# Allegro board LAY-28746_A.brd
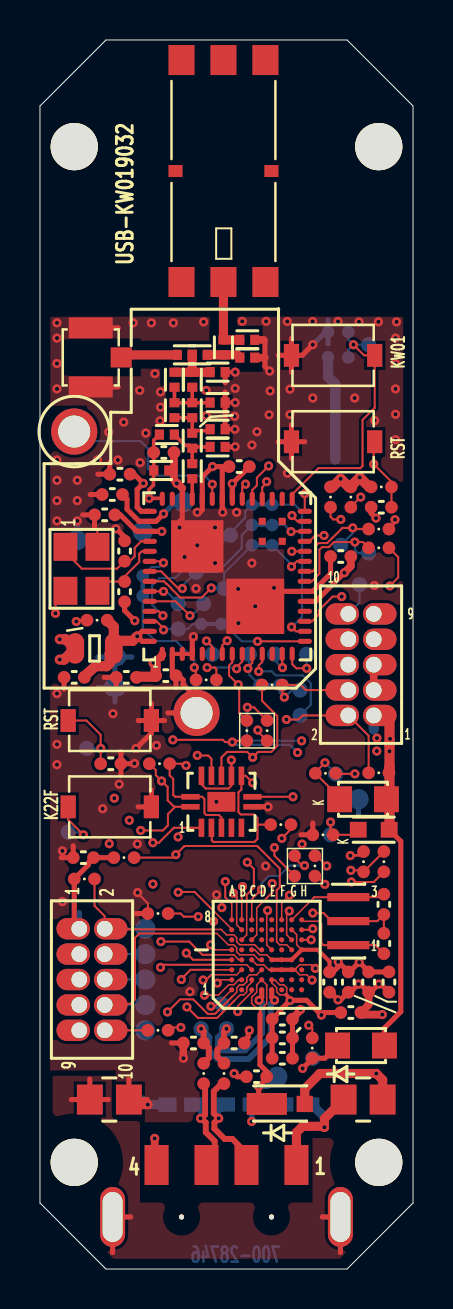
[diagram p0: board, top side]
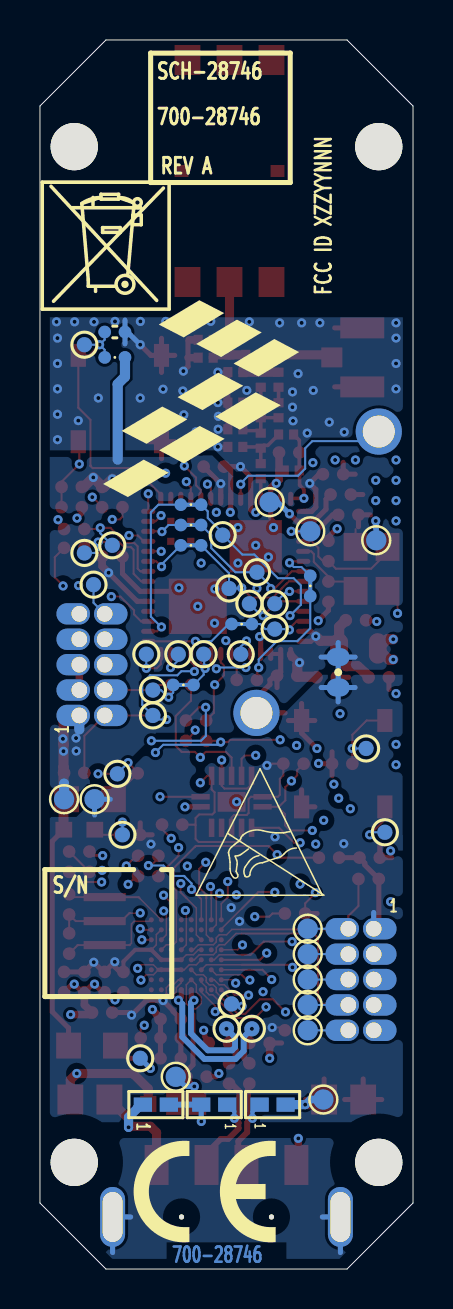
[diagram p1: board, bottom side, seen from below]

Outline 18.67 x 61.47 mm; copper layers: TOP, GND, SIGNAL, BOTTOM. Coordinates in mm from the lower left corner of the outline.
Outline path: 0,58.17 0,3.3 3.3,0 15.37,0 18.67,3.3 18.67,58.17 15.37,61.47 3.3,61.47 0,58.17

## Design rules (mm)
net group GA[0:7]: nets SWD_CLK_TGTMCU
net group GC[0:15]: nets RESET_TGTMCU_B
net group RF_7CLR: nets N23870337 N23870339 N23870349 RFIO
net group RF_18CLR: nets N23948926 N24026304 N24026588 RFIO_EXT
nets with their own width: min track width 0.254; nets VCC

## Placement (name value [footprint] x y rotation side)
ANT1  7488910092  [ANT_7488910092]  9.18 54.91 270 top
C4  5.6PF  [0402_CC]  8.89 44.86 0 top
C7  10PF  [0402_CC]  6.73 44.48 270 top
C9  7.5PF  [0402_CC]  8.89 43.33 0 top
C11  10PF  [0402_CC]  6.73 42.95 270 top
C13  6.8PF  [0402_CC]  7.62 41.43 90 top
C14  0.1UF  [CC0402_25]  6.2 40.84 0 top
C15  2.0PF  [0402_CC]  8.89 41.12 0 top
C16  220PF  [0402_CC]  6.07 39.94 0 top
C17  3.3PF  [0402_CC]  10.38 45.58 0 top
C19  0.1UF  [CC0402_25]  9.97 40.13 180 top
C20  3.3PF  [0402_CC]  10.38 46.47 0 top
C21  11PF  [CC0402_25]  4.23 35.91 90 top
C22  11PF  [CC0402_25]  4.23 33.88 270 top
C23  18PF  [CC0402_25]  17.21 16.28 270 top
C24  18PF  [CC0402_25]  17.21 18.24 90 top
C25  0.1UF  [CC0402_25]  4 39.75 180 top
C26  0.1UF  [CC0402_25]  4.32 29.59 180 top
C27  10UF  [CC0805_OV]  2.73 31.04 180 top
C28  0.1UF  [CC0402_25]  3.24 37.72 180 top
C31  0.1UF  [CC0402_25]  16.45 14.35 270 top
C32  2.2UF  [CC0402_25]  15.56 12.83 0 top
C33  0.1UF  [CC0402_25]  15.43 14.35 270 top
C34  0.1UF  [CC0402_25]  17.46 14.35 270 top
C36  0.1UF  [CC0402_25]  6.3 29.68 0 top
C37  47PF  [CC0402_25]  7.68 11.3 180 top
C38  47PF  [CC0402_25]  9.72 11.3 0 top
C39  0.1UF  [CC0402_25]  12.13 10.54 0 top
C42  0.1UF  [CC0402_25]  15.05 35.64 180 top
C43  0.01UF  [CC0402_25]  1.71 29.59 180 top
C44  0.1UF  [CC0402_25]  3.62 38.74 180 top
C46  10PF  [0402_CC]  8.89 42 0 top
C49  1.0UF  [CC0402_25]  10.84 9.62 180 top
C50  100PF  [0402_CC]  8 45.72 0 top
C51  1000PF  [CC0402_25]  14.92 46.86 180 bottom
C58  100PF  [0402_CC]  7.25 45.72 180 top
C60  1000PF  [CC0402_25]  17.08 38.1 180 top
C62  1000PF  [CC0402_25]  3.54 25.27 0 top
C66  0.1UF  [CC0402_25]  12.13 11.56 0 top
C67  0.1UF  [CC0402_25]  12.13 12.5 0 top
C68  0.1UF  [CC0402_25]  2.17 20.57 180 top
C69  0.01UF  [CC0402_25]  14.49 14.35 270 top
D4  GREEN  [LED_0603]  16.7 21.97 180 top
D8  BLUE  [LED2_2P34_2P1X1P25]  16.07 11.18 0 top
D12  BLUE  [LED2_2P34_2P1X1P25]  16.17 23.5 0 top
D18  MSS1P3L  [SMB_2P7X1P4]  12 8.26 0 top
J5  USB_TYPE_A  [MOLEX_480371000_USB_AM_SM]  9.33 2.6 0 top
J13  HDR 2X5  [CON_2RH_10_50]  1.97 17.02 270 top
J14  HDR 2X5  [CON_2RH_10_50]  16.7 27.69 90 top
J49  U.FL  [UFL_CONN3]  2.54 45.59 90 top
L2  0.0068UH  [0402_CC]  7.62 44.48 90 top
L3  10NH  [0402_CC]  9.18 46.09 90 top
L5  0.0068UH  [0402_CC]  7.62 42.95 90 top
L6  330 OHM  [IND_0805]  16.17 8.48 0 top
L7  330 OHM  [IND_0805]  3.47 8.48 0 top
L9  0.0047UH  [0402_CC]  7.62 39.9 90 top
L11  33nH  [0402_CC]  6.35 41.73 0 top
NOREF  -  []  -110.1 -101.68 0 top
NOREF#2  -  []  213.05 -126.24 0 top
NOREF#3  -  []  213 -99.57 0 top
NOREF#4  -  []  -105.39 -102.81 0 top
NOREF#5  -  []  0 56.24 0 top
NOREF#6  -  [unnamed#2]  16.95 5.33 0 top
NOREF#7  -  [unnamed#2]  1.71 56.13 0 top
NOREF#8  -  []  0 3.3 90 top
NOREF#9  -  []  -420.12 -277.37 0 top
NOREF#10  -  [unnamed#2]  1.71 5.33 0 top
NOREF#11  -  []  0 58.17 0 top
NOREF#12  -  []  3.3 61.47 0 top
NOREF#13  -  []  -208.12 -201.47 0 top
NOREF#14  -  []  -206.92 -205.2 0 top
NOREF#15  -  []  -39.12 -66.55 0 top
NOREF#16  -  []  167.39 109.22 0 top
NOREF#17  -  [unnamed#2]  16.95 56.13 0 top
NOREF#18  -  []  -207.76 -196.98 0 top
NOREF#19  -  []  3.3 0 90 top
NOREF#20  -  []  6.92 0 90 top
NOREF#21  -  []  -102.26 -96.66 0 top
NOREF#22  -  []  3.89 20.18 0 top
NOREF#23  -  []  -103.09 -101.68 0 top
NOREF#24  -  []  1.68 5.18 0 top
NOREF#25  -  []  -103.81 -197.14 0 top
NOREF#26  -  []  15.51 38.61 180 bottom
NOREF#27  -  []  12.97 1.02 180 bottom
NOREF#28  -  []  18.55 48.01 180 bottom
NOREF#29  -  []  10.83 18.69 180 bottom
R5  4.7K  [RC0402_25]  2.86 32.45 0 top
R10  220  [RC0402_25]  14.16 21.72 180 top
R11  0  [RC0402_25]  11.37 26.92 90 top
R14  0  [RC0402_25]  16.19 20.37 90 top
R15  0  [RC0402_25]  10.35 26.92 90 top
R17  0  [RC0402_25]  17.21 20.37 90 top
R25  10.0K  [RC0402_25]  16.95 24.82 0 top
R26  10.0K  [RC0402_25]  2.22 19.51 0 top
R30  220  [RC0402_25]  13.63 11.05 90 top
R31  220  [RC0402_25]  14.29 24.79 0 top
R50  33  [RC0402_25]  9.21 9.78 90 top
R51  33  [RC0402_25]  8.19 9.78 90 top
R53  4.7K  [RC0402_25]  15.56 38.61 270 top
R54  4.7K  [RC0402_25]  14.54 38.61 270 top
R85  100  [RC0402_25]  8.32 29.46 180 top
R88  1.0K  [RC0402_25]  12.74 20.16 90 top
R89  1.0K  [RC0402_25]  13.76 20.16 90 top
R90  1.0K  [RC0402_25]  16.95 37.01 180 top
R91  1.0K  [RC0402_25]  16.95 36.07 180 top
R92  1.0K  [RC0402_25]  12.05 22.23 0 top
R93  1.0K  [RC0402_25]  11.62 29.21 0 top
R105  10.0K  [RC0402_25]  5.98 25.27 0 top
R106  27K  [RC0402_25]  4.2 20.57 0 top
R112  27K  [RC0402_25]  5.91 17.78 180 top
R113  15K  [RC0402_25]  17.08 39.12 0 top
R114  15K  [RC0402_25]  5.91 11.94 180 top
R556  10.0K  [RC0402_25]  14.92 45.59 0 bottom
SH19  0  [RC0603_OV_CT]  3.75 29.85 90 bottom
SH40  0  [RC0402_25_CT]  11.11 37.21 0 bottom
SH41  0  [RC0402_25_CT]  11.11 36.2 0 bottom
SH44  0  [RC0402_25_CT]  5.14 34.16 90 bottom
SH45  0  [RC0402_25_CT]  8.57 32.26 0 bottom
SH46  0  [RC0402_25_CT]  11.11 38.23 0 bottom
SH47  0  [RC0402_25_CT]  11.49 29.21 180 bottom
SW1  TL1015AF160QG  [TL1015AF160QG_2P]  14.67 45.69 180 top
SW2  TL1015AF160QG  [TL1015AF160QG_2P]  3.49 23.11 0 top
SW5  TL1015AF160QG  [TL1015AF160QG_2P]  14.67 41.38 0 top
SW6  TL1015AF160QG  [TL1015AF160QG_2P]  3.49 27.43 180 top
TP2  -  [TPAD_040]  15.94 23.5 180 bottom
TP4  -  [TPAD_040]  17.46 23.5 180 bottom
TP8  -  [TPAD_030]  14.54 21.72 180 bottom
TP9  -  [TPAD_040]  1.84 36.45 180 bottom
TP10  -  [TPAD_040]  4.49 8.48 180 bottom
TP17  -  [TPAD_030]  13.65 10.54 180 bottom
TP21  -  [TPAD_030]  14.8 24.77 180 bottom
TP22  -  [TPAD_030]  9.33 12.01 180 bottom
TP23  -  [TPAD_030]  16.45 46.23 180 bottom
TP24  -  [TPAD_030]  8.62 30.75 180 bottom
TP25  -  [TPAD_030]  8.06 12.01 180 bottom
TP30  -  [TPAD_030]  1.41 21.84 180 bottom
TP32  -  [TPAD_030]  13.02 27.69 180 bottom
TP35  -  [TPAD_030]  15.99 34.23 180 bottom
TP36  -  [TPAD_030]  10.48 30.75 180 bottom
TP37  TESTLOOP_BLACK  [TP_TH_063]  1.71 41.88 0 top
TP42  -  [TPAD_030]  6.92 32 90 bottom
TP43  -  [TPAD_030]  9.53 36.7 180 bottom
TP44  -  [TPAD_030]  6.92 33.27 180 bottom
TP45  -  [TPAD_030]  8.19 33.27 180 bottom
TP46  -  [TPAD_040]  7.18 38.35 90 bottom
TP47  -  [TPAD_030]  9.21 34.04 90 bottom
TP48  -  [TPAD_040]  5.14 36.89 90 bottom
TP49  -  [TPAD_030]  7.81 34.85 180 bottom
TP51  -  [TPAD_030]  13.02 28.96 180 bottom
TP102  -  [TPAD_030]  9.08 13.26 0 bottom
TP104  -  [TPAD_040]  11.87 9.61 180 bottom
TP105  -  [TPAD_030]  2.35 26.04 180 bottom
TP113  -  [TPAD_030]  13.35 30.75 180 bottom
TP114  -  [TPAD_030]  11.75 30.75 180 bottom
TP116  -  [TPAD_030]  15.05 36.2 180 bottom
TP117  -  [TPAD_030]  16.45 35.81 180 bottom
TP507  TESTLOOP_BLACK  [TP_TH_063]  7.84 27.81 180 bottom
TP508  -  [TPAD_040]  5.27 17.02 270 bottom
TP509  -  [TPAD_040]  5.27 15.75 270 bottom
TP510  -  [TPAD_040]  5.27 14.48 270 bottom
TP511  -  [TPAD_040]  5.27 13.21 270 bottom
TP512  -  [TPAD_040]  5.27 11.94 270 bottom
TVS1  0402ESDA-MLP  [0402_MLP]  12.87 8.22 180 bottom
TVS2  0402ESDA-MLP  [0402_MLP]  7.03 8.22 180 bottom
TVS3  0402ESDA-MLP  [0402_MLP]  9.95 8.22 0 bottom
U1  MKW01Z128  [LGA60_0P5_8X8]  9.37 34.64 90 top
U7  MK22FN512VMP12  [MAPBGA64_0P5_5X5]  11.35 15.72 90 top
U8  74LVC125  [DQFN14_3X2P5MM]  9.08 23.37 0 top
X1  8.00MHZ  [XTAL3_3P35X1P45_SM]  15.43 17.4 270 top
Y1  32MHZ  [XTLOSC4_3P2X2P5MM_SM]  2.08 35.02 270 top

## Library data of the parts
ANT1 = ANT_Wurth_7488910092
C4 C9 C13-C17 C19-C25 C27 C28 C32 C36 C42-C44 C49-C51 C58 C60 C62 = CAP_NP
C7 C11 C37 C38 C46 = CAP_NP: tolerance: 5%
C26 C31 C33 C34 C39 C66-C68 = CAP_NP: tolerance: 10%
C69 = CAP_NP: tolerance: 20%
D4 D8 D12 = LED
D18 = DIODE_SCHTKY
J5 = USB_A
J13 J14 = CONN_HDR_5X2: User Part Number: XXX-XXXXX-00
J49 = UFL_CONN
L2 L3 L5 L9 L11 = INDUCTOR
L6 L7 = BEAD
R5 R10 R11 R15 R30 R31 R50 R51 R53 R54 R85 R106 R112 = RES
R14 R17 = RES: tolerance: 5%
R25 R26 R88-R93 R105 R113 R114 R556 = RES: tolerance: 1%
SH19 SH40 SH41 SH44-SH47 = SH_RES
SW1 SW2 SW5 SW6 = SW_TACT-SPST-2_SMD
TP2 TP4 TP9 TP10 TP37 TP46 TP48 TP104 TP507-TP512 = TestLoop
TP8 TP17 TP21-TP25 TP30 TP32 TP35 TP36 TP42-TP45 TP47 TP49 TP51 TP102 TP105 TP113 TP114 TP116 TP117 = TESTLOOP
TVS1-TVS3 = DIODE_TVS_BIDIR
U1 = MKW01Z128_LGA_0
U7 = MK22FN512_BGA_64P
U8 = 74LVC125_DHVQFN_14P
X1 = XTAL_CS
Y1 = XTAL_13Y

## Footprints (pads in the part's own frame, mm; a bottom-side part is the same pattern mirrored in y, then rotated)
0402_CC
  rect 0.457x0.508 smd: 1(-0.375,0) 2(0.375,0)
0402_MLP
  rect 0.914x0.711 smd: 1(-0.65,0) 2(0.65,0)
ANT_7488910092
  rect 1.5x1.3 smd: (-5.55,2.1) (-5.55,0) (-5.55,-2.1) (5.55,2.1) (5.55,-2.1) 2(5.55,0)
  rect 0.6x0.7 smd: (0,2.4) (0,-2.4)
CC0402_25
  round 0.635 smd: 1(-0.508,0) 2(0.508,0)
CC0805_OV
  oval 0.889x1.524 smd: 1(-0.965,0) 2(0.965,0)
CON_2RH_10_50
  oval 1.067x1.676 hole 0.787: 1(0,0) 2(0,1.27) 3(1.27,0) 4(1.27,1.27) 5(2.54,0) 6(2.54,1.27) 7(3.81,0) 8(3.81,1.27) 9(5.08,0) 10(5.08,1.27)
DQFN14_3X2P5MM
  rect 0.914x0.279 smd: 1(-1.55,-0.25) 7(1.55,-0.25) 8(1.55,0.25) 14(-1.55,0.25)
  rect 0.279x0.914 smd: 2(-1,-1.3) 3(-0.5,-1.3) 4(0,-1.3) 5(0.5,-1.3) 6(1,-1.3) 9(1,1.3) 10(0.5,1.3) 11(0,1.3) 12(-0.5,1.3) 13(-1,1.3)
  rect 1.397x0.991 smd: 15(0,0)
IND_0805
  rect 1.295x1.499 smd: 1(-0.978,0) 2(0.978,0)
LED2_2P34_2P1X1P25
  rect 1.245x1.295 smd: A(1.172,0) C(-1.172,0)
LED_0603
  rect 0.838x0.787 smd: A(-0.775,0) C(0.775,0)
LGA60_0P5_8X8
  oval 0.711x0.254 smd: 1(-3.878,3.25) 2(-3.878,2.75) 3(-3.878,2.25) 4(-3.878,1.75) 5(-3.878,1.25) 6(-3.878,0.75) 7(-3.878,0.25) 8(-3.878,-0.25) 9(-3.878,-0.75) 10(-3.878,-1.25) 11(-3.878,-1.75) 12(-3.878,-2.25) 13(-3.878,-2.75) 14(-3.878,-3.25) 29(3.878,-3.25) 30(3.878,-2.75) 31(3.878,-2.25) 32(3.878,-1.75) 33(3.878,-1.25) 34(3.878,-0.75) 35(3.878,-0.25) 36(3.878,0.25) 37(3.878,0.75) 38(3.878,1.25) 39(3.878,1.75) 40(3.878,2.25) 41(3.878,2.75) 42(3.878,3.25)
  oval 0.254x0.711 smd: 15(-3.25,-3.878) 16(-2.75,-3.878) 17(-2.25,-3.878) 18(-1.75,-3.878) 19(-1.25,-3.878) 20(-0.75,-3.878) 21(-0.25,-3.878) 22(0.25,-3.878) 23(0.75,-3.878) 24(1.25,-3.878) 25(1.75,-3.878) 26(2.25,-3.878) 27(2.75,-3.878) 28(3.25,-3.878) 43(3.25,3.878) 44(2.75,3.878) 45(2.25,3.878) 46(1.75,3.878) 47(1.25,3.878) 48(0.75,3.878) 49(0.25,3.878) 50(-0.25,3.878) 51(-0.75,3.878) 52(-1.25,3.878) 53(-1.75,3.878) 54(-2.25,3.878) 55(-2.75,3.878) 56(-3.25,3.878)
  rect 0.356x0.356 smd: 57(1.75,-1.75) 58(2.75,-1.75) 59(1.75,-2.75) 60(2.75,-2.75)
  rect 2.769x2.896 smd: 61(-1.5,-1.4)
  rect 2.616x2.616 smd: 62(1.5,1.5)
MAPBGA64_0P5_5X5
  round 0.254 smd: A1(-1.75,1.75) A2(-1.25,1.75) A3(-0.75,1.75) A4(-0.25,1.75) A5(0.25,1.75) A6(0.75,1.75) A7(1.25,1.75) A8(1.75,1.75) B1(-1.75,1.25) B2(-1.25,1.25) B3(-0.75,1.25) B4(-0.25,1.25) B5(0.25,1.25) B6(0.75,1.25) B7(1.25,1.25) B8(1.75,1.25) C1(-1.75,0.75) C2(-1.25,0.75) C3(-0.75,0.75) C4(-0.25,0.75) C5(0.25,0.75) C6(0.75,0.75) C7(1.25,0.75) C8(1.75,0.75) D1(-1.75,0.25) D2(-1.25,0.25) D3(-0.75,0.25) D4(-0.25,0.25) D5(0.25,0.25) D6(0.75,0.25) D7(1.25,0.25) D8(1.75,0.25) E1(-1.75,-0.25) E2(-1.25,-0.25) E3(-0.75,-0.25) E4(-0.25,-0.25) E5(0.25,-0.25) E6(0.75,-0.25) E7(1.25,-0.25) E8(1.75,-0.25) F1(-1.75,-0.75) F2(-1.25,-0.75) F3(-0.75,-0.75) F4(-0.25,-0.75) F5(0.25,-0.75) F6(0.75,-0.75) F7(1.25,-0.75) F8(1.75,-0.75) G1(-1.75,-1.25) G2(-1.25,-1.25) G3(-0.75,-1.25) G4(-0.25,-1.25) G5(0.25,-1.25) G6(0.75,-1.25) G7(1.25,-1.25) G8(1.75,-1.25) H1(-1.75,-1.75) H2(-1.25,-1.75) H3(-0.75,-1.75) H4(-0.25,-1.75) H5(0.25,-1.75) H6(0.75,-1.75) H7(1.25,-1.75) H8(1.75,-1.75)
MOLEX_480371000_USB_AM_SM
  round 0.254 hole 1.092 unplated: (-2.25,0) (2.25,0)
  rect 1.2x2 smd: A1(3.5,2.6) A2(1,2.6) A3(-1,2.6) A4(-3.5,2.6)
  oval 1.25x3 hole 1x2.5: S1(-5.7,0) S2(5.7,0)
RC0402_25
  round 0.635 smd: 1(-0.508,0) 2(0.508,0)
RC0402_25_CT
  round 0.635 smd: 1(-0.508,0) 2(0.508,0)
RC0603_OV_CT
  oval 0.889x1.143 smd: 1(-0.762,0) 2(0.762,0)
SMB_2P7X1P4
  rect 0.813x0.813 smd: A(1.25,0)
  rect 2.007x1.092 smd: C(-0.65,0)
TL1015AF160QG_2P
  rect 0.762x1.143 smd: 1(-2.083,0) 2(2.083,0)
TP_TH_063
  round 2.311 hole 1.6: 1(0,0)
TPAD_030
  round 0.762 smd: 1(0,0)
TPAD_040
  round 1.016 smd: 1(0,0)
UFL_CONN3
  rect 1x1.05 smd: 1(0,-1.525)
  rect 1.05x2.2 smd: 2(-1.475,0) 3(1.475,0)
unnamed#2
  round 2.362 hole 2.362 unplated: (0,0)
XTAL3_3P35X1P45_SM
  rect 0.406x2.108 smd: 1(1.2,0) 2(0,0) 3(-1.2,0)
XTLOSC4_3P2X2P5MM_SM
  rect 1.397x1.194 smd: 1(-1.1,-0.8) 2(1.1,-0.8) 3(1.1,0.8) 4(-1.1,0.8)

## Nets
GND: C4.2 C9.2 C14.2 C15.2 C16.2 C17.2 C19.2 C20.2 C21.2 C22.2 C23.1 C24.1 C25.2 C26.2 C27.2 C28.2 C31.2 C32.2 C33.2 C34.2 C36.2 C37.2 C38.2 C39.2 C42.2 C43.2 C44.2 C46.2 C49.2 C51.2 C60.2 C62.2 C66.2 C67.2 C68.2 C69.2 J5.A4(GND) J13.3(A2) J13.5(A3) J14.3(A2) J14.5(A3) J49.2(SHIELD1) J49.3(SHIELD2) L7.2 R10.2 R17.1 R112.2 SW1.2 SW2.2 SW5.1 SW6.1 TP9.1(PIN1) TP10.1(PIN1) TP507.1(PIN1) TVS1.2(A2) TVS2.2(A2) TVS3.2(A2) U1.2(VREFL) U1.3(VSSA) U1.4(VSS1#4) U1.20(VSS1#20) U1.36(GND/SCAN) U1.38(GND_PA2) U1.40(GND_PA1) U1.61(FLAG1) U1.62(FLAG2) U7.C4(VSS1) U7.E3(VSS3) U7.F3(VSSA) U7.G3(VREFL) U7.H7(VSS2) U8.7(GND) U8.15(EP) X1.2 Y1.2 Y1.4
P3V3_K22F: C31.1 C32.1 C33.1 C34.1 C39.1 C66.1 C67.1 C68.1 C69.1 J13.1(A1) R26.1 R105.2 R106.1 R114.1 SH19.1 TP2.1(PIN1) U7.C5(VDD1) U7.E2(VOUT33) U7.E4(VDD3) U7.F4(VDDA) U7.G4(VREFH) U7.G7(VDD2) U7.H5(VBAT) U8.4(2\O\E\) U8.14(VCC)
VCC: C19.1 C25.1 C26.1 C27.1 C36.1 C42.1 C43.1 D4.A(ANODE) D8.A(ANODE) D12.A(ANODE) J14.1(A1) R5.2 R25.2 R53.1 R54.1 R113.1 R556.1 SH19.2 TP4.1(PIN1) U1.1(VREFH) U1.19(VDD#19) U1.35(VBAT2) U1.43(VBAT1) U1.55(VDD#55) U1.56(VDDA)
DIO0: SH40.1 TP49.1(PIN1) U1.49(DIO0/PTE2)
DIO1: SH41.1 TP47.1(PIN1) U1.50(DIO1/PTE3)
DIO4: SH46.1 TP43.1(PIN1) U1.53(DIO4)
DIO5/CLKOUT: SH45.1 TP42.1(PIN1) U1.54(DIO5/CLKOUT)
EXTAL0: C23.2 U7.H8(PTA18/EXTAL0/FTM0_FLT2/FTM_CLKIN0) X1.1
EXTAL_32M: C21.1 U1.46(XTA) Y1.1
JTAG_TCLK_K22F: J13.4(B2) TP509.1(PIN1) U7.D3(PTA0/JTAG_TCLK/SWD_CLK/EZP_CLK/U\A\R\T\0\_\C\T\S\/FTM0_CH5)
JTAG_TDI_K22F: J13.8(B4) TP511.1(PIN1) U7.D4(PTA1/JTAG_TDI/EZP_DI/UART0_RX/FTM0_CH6)
JTAG_TDO_K22F: J13.6(B3) TP510.1(PIN1) U7.E5(PTA2/JTAG_TDO/TRACE_SWO/EZP_DO/UART0_TX/FTM0_CH7)
JTAG_TMS_K22F: J13.2(B1) R26.2 TP508.1(PIN1) U7.D5(PTA3/JTAG_TMS/SWD_DIO/U\A\R\T\0\_\R\T\S\/FTM0_CH0)
PTA0/SWD_CLK: SH47.2 TP36.1(PIN1) U1.10(PTA0/SWD_CLK)
PTA1/UART0_RX: R89.2 TP113.1(PIN1) U1.14(PTA1/DISABLED)
PTA2/UART0_TX: R88.1 TP114.1(PIN1) U1.13(PTA2/DISABLED)
PTA3/SWD_DIO: J14.2(B1) R25.1 R92.2 TP32.1(PIN1) U1.11(PTA3/SWD_DIO)
PTA12_K22F/LED: R30.2 U7.H6(PTA12/FTM1_CH0/I2S0_TXD0/FTM1_QD_PHA)
PTA13_K22F/SW: SW2.1 TP30.1(PIN1) U7.G6(PTA13/LLWU_P4/FTM1_CH1/I2S0_TX_FS/FTM1_QD_PHB)
PTA18: SH45.2 U1.15(PTA18/EXTAL0)
PTA19: SH46.2 U1.16(PTA19/XTAL0)
PTB0: R31.2 U1.17(PTB0)
PTB2: R91.2 TP117.1(PIN1) U1.21(PTB2)
PTB17: R90.2 TP116.1(PIN1) U1.22(PTB17)
PTC1: U1.24(PTC1/ADC0_SE15) U7.B4(PTC10/ADC1_SE6B/I2C1_SCL/FTM3_CH6/I2S0_RX_FS/FB_AD5)
PTC2: U1.25(PTC2/ADC0_SE11) U7.A5(PTC11/LLWU_P11/ADC1_SE7B/I2C1_SDA/FTM3_CH7/F\B\_\R\W\)
PTC3: SH40.2 U1.26(PTC3)
PTC4: SH41.2 U1.23(PTC4/DISABLED)
PTD4_SPI1_PCS0: U1.27(PTD4) U7.C3(PTD0/LLWU_P12/SPI0_PCS0/U\A\R\T\2\_\R\T\S\/FTM3_CH0/FB_ALE/F\B\_\C\S\1\/F\B\_\T\S\/L\P\U\A\R\T\0\_\R\T\S\)
PTD5_SPI1_SCK: U1.28(PTD5) U7.A4(PTD1/ADC0_SE5B/SPI0_SCK/U\A\R\T\2\_\C\T\S\/FTM3_CH1/F\B\_\C\S\0\/L\P\U\A\R\T\0\_\C\T\S\)
PTD6: C51.1 R556.2 SW1.1 TP23.1(PIN1) U1.29(PTD6)
PTE0_SPI1_MISO: U1.32(PTE0/DISABLED) U7.B6(PTC7/CMP0_IN1/SPI0_SIN/USB_SOF_OUT/I2S0_RX_FS/FB_AD8)
PTE1_SPI1_MOSI: U1.34(PTE1) U7.A7(PTC6/LLWU_P10/CMP0_IN0/SPI0_SOUT/PDB0_EXTRG/I2S0_RX_BCLK/FB_AD9/I2S0_MCLK)
PTE18_I2C0_SDA: R11.2 R53.2 U7.B3(PTD3/SPI0_SIN/UART2_TX/FTM3_CH3/FB_AD3/LPUART0_TX/I2C0_SDA)
PTE19_I2C0_SCL: R15.1 R54.2 U7.C2(PTD2/LLWU_P13/SPI0_SOUT/UART2_RX/FTM3_CH2/FB_AD4/LPUART0_RX/I2C0_SCL)
PTE30: R85.1 U1.9(PTE30/DAC_OUT/ADC0_SE23/CMP0_IN4)
R_SWD_DIO_TGTMCU: R92.1 U8.3(1Y) U8.9(3A)
RESET_B_TGTMCU: R14.1 R17.2 U7.A8(PTC5/LLWU_P9/SPI0_SCK/LPTMR0_ALT2/I2S0_RXD0/FB_AD10/CMP0_OUT/FTM0_CH2)
RESET_B_XCVR: R5.1 SH44.2 U1.48(RESET)
RESET_TGTMCU_B: C60.1 J14.10(B5) R14.2 R113.2 SW5.2 TP35.1(PIN1) U1.33(PTA20/RESET_B)
RFIO: L9.1 U1.39(RFIO)
RFIO_EXT: C4.1 C7.1 C50.1 C58.1 L2.2
RST_K22F: C62.1 J13.10(B5) R114.2 SW6.2 TP105.1(PIN1) TP512.1(PIN1) U7.F8(R\E\S\E\T\)
SDA_SPI0_SCK: U7.C1(PTD5/ADC0_SE6B/SPI0_PCS2/U\A\R\T\0\_\C\T\S\/FTM0_CH5/FB_AD1/E\W\M\_\O\U\T\/SPI1_SCK) U8.12(4A)
SDA_SPI0_SIN: R112.1 U7.A2(PTD7/UART0_TX/FTM0_CH7/FTM0_FLT1/SPI1_SIN) U8.8(3Y)
SDA_SPI0_SOUT: U7.B2(PTD6/LLWU_P15/ADC0_SE7B/SPI0_PCS3/UART0_RX/FTM0_CH6/FB_AD0/FTM0_FLT0/SPI1_SOUT) U8.2(1A)
SDA_SWD_EN: R106.2 U7.G5(PTA4/LLWU_P3/N\M\I\/E\Z\P\_\C\S\/FTM0_CH1) U8.10(3\O\E\) U8.13(4\O\E\)
SDA_SWD_OE_B: R105.1 U7.A3(PTD4/LLWU_P14/SPI0_PCS1/U\A\R\T\0\_\R\T\S\/FTM0_CH4/FB_AD2/EWM_IN/SPI1_PCS0) U8.1(1\O\E\)
SWD_CLK_TGTMCU: J14.4(B2) R93.2 SH47.1 TP51.1(PIN1)
UART1_CTS_TGTMCU: R90.1 U7.C6(PTC1/LLWU_P6/ADC0_SE15/SPI0_PCS3/U\A\R\T\1\_\R\T\S\/FTM0_CH0/FB_AD13/I2S0_TXD0/L\P\U\A\R\T\0\_\R\T\S\)
UART1_RTS_TGTMCU: R91.1 U7.B7(PTC2/ADC0_SE4B/CMP1_IN0/SPI0_PCS2/U\A\R\T\1\_\C\T\S\/FTM0_CH1/FB_AD12/I2S0_TX_FS/L\P\U\A\R\T\0\_\C\T\S\)
UART1_RX_TGTMCU: R89.1 U7.B8(PTC4/LLWU_P8/SPI0_PCS0/UART1_TX/FTM0_CH3/FB_AD11/CMP1_OUT/LPUART0_TX)
UART1_TX_TGTMCU: R88.2 U7.C8(PTC3/LLWU_P7/CMP1_IN1/SPI0_PCS1/UART1_RX/FTM0_CH2/CLKOUT/I2S0_TX_BCLK/LPUART0_RX)
USBDM: C38.1 R50.2 TP22.1(PIN1) U7.D1(USB0_DM)
USBDP: C37.1 R51.2 TP25.1(PIN1) U7.E1(USB0_DP)
VR_ANA: C44.1 TP46.1(PIN1) U1.44(VR_ANA)
VR_DIG: C28.1 TP48.1(PIN1) U1.45(VR_DIG)
VR_PA: C14.1 C16.1 L11.1 U1.42(VR_PA)
VUSB: C49.1 D18.C TP104.1(PIN1) U7.D2(VREGIN)
XTAL0: C24.2 U7.G8(PTA19/XTAL0/FTM1_FLT0/FTM_CLKIN1/LPTMR0_ALT1) X1.3
XTAL_32M: C22.1 U1.47(XTB) Y1.3
N23869826: TP37.1(PIN1) U1.37(RXTX)
N23870337: C13.1 C15.1 L9.2 L11.2
N23870339: C11.2 C13.2 C46.1 L5.1
N23870349: C7.2 C9.1 C11.1 L2.1 L5.2
N23913269: R85.2 SH44.1
N23948926: C58.2 J49.1(CENTER)
N23974000: D12.C(CATHODE) R31.1 TP21.1(PIN1)
N24026304: C17.1 C50.2 L3.1
N24026588: ANT1.2(FEED) C20.1 L3.2
N24037103: R11.1 U1.7(PTE18/ADC0_DP2/ADC0_SE2)
N24037421: R15.2 U1.8(PTE19/ADC0_DM2/ADC0_SE6A)
N24069474: TP24.1(PIN1) U1.6(PTE17/ADC0_DM1/ADC0_SE5A)
N24071066: TP44.1(PIN1) U1.51(DIO2)
N24071069: TP45.1(PIN1) U1.52(DIO3)
N24103085: J5.A1(VCC) L6.1 TVS1.1(A1)
N24103119: J5.S1(SGND1) J5.S2(SGND2) L7.1
N24103131: J5.A2(DATA+) R50.1 TVS3.1(A1)
N24103151: J5.A3(DATA-) R51.1 TVS2.1(A1)
N24103276: D18.A L6.2
N24103280: D8.C(CATHODE) R30.1 TP17.1(PIN1)
N24103316: D4.C(CATHODE) R10.1 TP8.1(PIN1)
N24103468: TP102.1(PIN1) U7.A1(PTE0/CLKOUT32K/ADC1_SE4A/SPI1_PCS1/UART1_TX/I2C1_SDA/RTC_CLKOUT)
N24109842: R93.1 U8.11(4Y)

Pads without a net: J13 7 9; J14 6 7 8 9; U1 5 12 18 30 31 41 57 58 59 60; U7 A6 B1 B5 C7 D6 D7 D8 E6 E7 E8 F1 F2 F5 F6 F7 G1 G2 H1 H2 H3 H4; U8 5 6

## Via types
v1: diameter 0.457, hole 0.203, TOP to BOTTOM, 248 vias

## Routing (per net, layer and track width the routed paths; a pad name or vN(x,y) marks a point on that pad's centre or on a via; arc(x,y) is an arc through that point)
GND: length 124.5
  TOP w0.076: 14.16,17.8 13.66,17.8 v1(13.65,17.81) ; U7.E3 11.45,14.96 11.2,15.21 10.85,15.21 U7.C4 ; v1(13.62,14.45) 13.35,14.72 12.99,14.72 12.74,14.96 12.99,15.22 13.6,15.22 v1(13.78,15.04)
  TOP w0.102: v1(15.58,19.35) 16.7,19.35 R17.1 ; v1(0.77,32.79) 0.77,33.42 Y1.2 ; 14.16,17.8 14.2,17.8 14.59,17.4 X1.2 16.88,17.4 C24.1 C23.1 ; Y1.4 2.88,37 ; v1(6.85,39.29) 6.88,39.29 ; v1(13.65,17.02) 13.6,16.97 U7.H7 ; R112.2 5.4,18.29 4.89,18.8 4.89,18.83 v1(4.89,18.83) ; v1(7.24,35.61) 7.82,36.2 v1(7.87,36.2)
  TOP w0.203: C9.2 v1(9.77,43.33) ; 12.74,14.96 U7.G3 U7.F3 U7.E3 ; C46.2 v1(9.75,42) ; 7.12,37.55 6.98,37.41 v1(6.98,37.08) ; U1.4 U1.3 U1.2 ; C4.2 v1(9.77,44.86)
  TOP w0.254: 12.59,40.53 SW5.1 ; SW5.1 13.25,41.38 ; SW5.1 12.59,42.23 ; SW5.1 11.93,41.38 ; C15.2 9.76,41.12 v1(9.77,41.12) ; v1(13.65,46.23) 13.12,45.69 SW1.2 ; v1(7.87,37.85) 8,37.85 8.12,37.97 U1.38 8.12,39.62 v1(8.64,40.13) 9.12,40.13 ; v1(4.75,32.42) 4.23,32.94 C22.2 ; C34.2 17.06,14.25 v1(16.95,14.25) 16.55,13.84 C31.2 16.04,14.25 v1(15.94,14.25) 15.53,13.84 C33.2 15.02,13.43 14.95,13.43 14.92,13.46 v1(14.91,13.46) 14.53,13.84 C69.2 ; v1(10.48,11.94) 10.42,11.88 10.42,11.61 10.22,11.42 C38.2 ; 13.65,22.31 R10.2 13.06,21.72 ; 1.66,21.17 C68.2 1.07,20.57 ; 2.51,38.74 C44.2 ; 12.59,44.84 SW1.2 ; SW1.2 11.93,45.69 ; SW1.2 12.59,46.55 ; v1(11.71,34.07) 11.89,33.89 U1.20 13.66,33.89 14.54,34.78 C42.2 ; C49.2 9.88,9.62 v1(9.72,9.78) ; J49.2 3.92,44.12 ; 11.2,46.47 11.26,46.41 11.26,45.14 v1(11.49,44.91) ; v1(4.81,26.04) 5.58,26.8 SW6.1 ; 2.73,37.12 C28.2 2.13,37.72 ; C39.2 C66.2 C67.2 ; 4.45,9.5 L7.2 5.38,8.48 ; U8.7 11.37,23.12 ; C36.2 6.62,29.86 U1.2 ; C36.2 6.95,29.68 7.16,29.46 7.16,29.24 7.84,28.56 TP507.1 6.4,27.81 ; C36.2 6.81,29.08 ; 6.58,11.3 C37.2 ; SW6.1 6.24,27.43 ; SW6.1 4.91,27.43 ; SW6.1 5.58,28.28 ; v1(3.8,37.02) 3.8,37.05 4.23,36.61 C21.2 ; U1.4 7.62,31.57 v1(7.68,31.63) ; C46.2 9.27,42.53 ; 3.22,29.59 C26.2 3.82,28.99 ; 9.27,43.87 C9.2 9.27,42.8 ; C62.2 4.05,25.87 ; C62.2 4.05,24.67 ; C62.2 4.65,25.27 ; C60.2 16.57,37.8 v1(16.81,37.55) ; 2.9,39.75 C25.2 3.49,40.35 ; 5.58,23.96 SW2.2 4.91,23.11 ; 1.21,28.99 C43.2 ; 9.12,40.13 U1.36 9.12,38.06 9.17,38.01 9.17,37.87 v1(9.14,37.85) ; 9.12,40.13 C19.2 ; J49.3 3.92,47.07 ; 7.12,37.55 U1.40 7.12,39.05 ; 9.27,44.32 C4.2 ; 4.8,17.78 R112.2
  TOP w0.381: 6.71,39.94 C16.2 ; 6.71,39.94 6.71,39.47 7.12,39.05 ; 6.71,39.94 C14.2 ; C37.2 v1(7.18,10.54) ; 11.2,46.47 C20.2 ; J14.3 J14.5 ; v1(5.74,6.53) 5.74,5.3 J5.A4 ; C67.2 v1(13.04,12.98) ; v1(17.13,12.73) 16.17,12.73 C32.2 16.45,13.21 C31.2 ; C17.2 11.26,45.58
  TOP w0.457: L7.2 4.7,8.22 v1(5.4,8.22)
  TOP w0.508: v1(0.99,31.5) 1.29,31.5 1.75,31.03 ; C27.2 1.75,31.03 ; 1.75,31.03 1.21,30.48 v1(0.99,30.48)
  GND w0.203: 18.05,26.54 18.05,28.22 17.31,28.96 J14.3 ; 0.94,9.75 0.61,10.08 0.61,13.91 1.18,14.48 J13.5 ; 18.05,33.83 18.05,30.96 17.31,30.23 J14.5 ; J13.3 0.88,15.75 0.61,16.01 0.61,18.99
  GND w0.254: TP507.1 7.84,29.25 ; TP507.1 6.4,27.81 ; TP507.1 7.84,26.38 ; TP507.1 9.27,27.81
  SIGNAL w0.381: J13.5 J13.3
  BOTTOM w0.254: v1(10.59,7.38) 10.59,7.54 10.6,7.54 TVS3.2 ; C51.2 14.41,47.46 ; C51.2 14.29,46.86 v1(13.65,46.23) ; C51.2 14.41,46.27 ; v1(1.87,37.41) 1.84,37.39 1.84,37.2 1.87,37.07 1.84,37 TP9.1
  BOTTOM w0.292: TVS3.2 TVS1.2
  BOTTOM w0.381: TP10.1 5.14,8.48 v1(5.4,8.22)
  BOTTOM w0.457: TVS2.2 v1(5.4,8.22)
  vias: v1(0.85,47.32) v1(0.85,46.56) v1(0.85,45.29) v1(0.85,44.02) v1(0.85,40.46) v1(0.85,39.45) v1(0.85,38.43) v1(0.85,37.41) v1(0.85,28.78) v1(0.85,26.24) v1(0.85,25.22) v1(1.12,20.91) v1(1.12,18.37) v1(1.87,39.45) v1(1.87,38.43) v1(2.88,40.46) v1(3.14,23.02) v1(3.44,41.86) v1(3.65,27.77) v1(3.9,40.46) v1(3.96,24.25) v1(4.19,42.35) v1(4.66,47.32) v1(4.73,25.29) v1(4.87,21.25) v1(4.99,43.94) v1(5.01,40.33) v1(5.3,41.81) v1(5.58,47.32) v1(5.75,44.78) v1(5.83,26.19) v1(6.03,43.87) v1(6.03,43.1) v1(6.01,42.42) v1(6.68,47.32) v1(7.51,13.87) v1(7.81,34.04) v1(8.19,47.37) v1(8.32,43.94) v1(8.32,42.67) v1(8.76,37.08) v1(8.76,35.31) v1(8.83,23.37) v1(8.84,18.71) v1(9.74,42.65) v1(9.77,44.04) v1(9.84,37.85) v1(9.92,34.01) v1(9.93,32.3) v1(10.12,47.4) v1(10.61,41.21) v1(10.6,35.31) v1(10.86,41.88) v1(10.77,33.14) v1(11.32,47.4) v1(11.3,20.15) v1(11.41,23.11) v1(11.52,43.92) v1(11.47,42.72) v1(12.37,47.39) v1(12.38,39.8) v1(12.51,44.01) v1(12.51,42.74) v1(13.64,47.39) v1(13.65,43.56) v1(14.91,47.39) v1(15.75,43.56) v1(15.96,47.37) v1(16.75,42.43) v1(16.74,34.18) v1(16.94,47.37) v1(17.84,47.37) v1(17.79,46.56) v1(17.79,45.29) v1(17.79,44.02) v1(17.79,42.75) v1(17.79,41.48)
P3V3_K22F: length 37
  TOP w0.076: U7.E4 11.34,15.72 10.99,15.72 10.74,15.97 U7.C5 ; U7.G7 12.61,16.97 12.85,16.72 12.85,16.21 U7.H5 ; 11.74,14.46 U7.E2 11.6,14.32 11.85,14.07 11.85,13.86 11.99,13.72 12.32,13.72 12.35,13.75 12.35,14.07 12.2,14.21 11.99,14.21 11.74,14.46
  TOP w0.102: v1(7.31,25.19) 7.14,25.19 7.05,25.27 R105.2 6.49,24.69 6.67,24.51 6.67,23.71 6.76,23.62 U8.14 8.12,23.62 8.23,23.51 8.23,22.8 8.32,22.71 8.95,22.71 9.08,22.58 U8.4 ; R114.1 6.56,12.08 v1(7.05,12.08)
  TOP w0.203: 12.32,13.72 12.51,13.52 v1(12.51,13.43) ; C69.1 14.49,15.38 13.91,15.97 U7.H5 U7.G4 U7.F4 U7.E4
  TOP w0.254: 14.21,12.82 v1(14.08,12.7) 13.35,13.44 12.52,13.44 v1(12.51,13.43) 12.01,12.92 12.01,12.88 C67.1 C66.1 C39.1 ; 14.21,12.82 14.21,12.83 ; 14.21,12.82 14.21,12.83 14.21,12.83 ; 14.21,12.83 C32.1 ; J13.1 1.71,17.27 R26.1 2.41,20.21 2.41,20.31 C68.1 R106.1 ; C34.1 C31.1 16.45,14.87 v1(15.98,15.34) 15.49,14.86 C33.1 v1(14.93,15.36) 14.93,15.11 14.67,14.86 C69.1
  SIGNAL w0.254: J13.1 1.97,17.83
  BOTTOM w0.254: 3.75,28.36 SH19.1 ; SH19.1 4.6,29.08 ; SH19.1 2.9,29.08 ; 15.94,22.71 TP2.1 15.15,23.5 ; J13.1 1.97,17.83
  vias: v1(3.47,21.27) v1(6.91,21.61) v1(8.68,17.39) v1(9.1,18.07) v1(13.12,21.25)
VCC: length 48.6
  TOP w0.254: D8.A 17.24,12.05 18.06,12.87 18.06,21.39 D4.A ; U1.35 v1(9.62,39.28) C19.1 ; U1.19 13.8,33.39 v1(15.23,34.82) ; U1.55 5.11,31.89 v1(4.86,31.64) 5.11,31.39 U1.56 ; C25.1 4.71,39.75 v1(5.17,39.29) 4.86,38.99 4.86,38.1 5.07,37.89 U1.43 ; 3.7,31.14 C27.1
  TOP w0.381: v1(15.23,34.82) 15.56,35.15 C42.1 ; v1(5.68,30.33) 5.74,30.33 6.12,30.71 U1.1
  TOP w0.508: 17.49,25.12 R25.2 ; 17.49,25.12 17.49,23.65 D12.A 17.49,23.34 17.49,21.99 D4.A ; 17.49,25.12 17.49,26.23 17.48,26.23 17.49,26.3 17.49,27.69 J14.1 ; R54.1 14.64,39.12 v1(15.05,39.52) 15.45,39.12 R53.1 15.56,39.14 v1(16,39.59) 16.47,39.12 R113.1 ; C27.1 3.7,30.98 3.49,30.78 3.49,30.3 3.34,30.15 2.78,30.15 2.23,29.66 C43.1 ; C26.1 4.86,29.62 5.74,29.62 C36.1 5.79,30.22 v1(5.68,30.33) ; R5.2 3.7,32.12 3.7,31.14 3.98,31.42 4.64,31.42 v1(4.86,31.64)
  SIGNAL w0.254: 16.7,26.87 J14.1
  BOTTOM w0.254: SH19.2 3.75,31.33 ; SH19.2 2.9,30.61 ; SH19.2 4.6,30.61
  BOTTOM w0.508: 14.78,40.48 14.78,44.26 14.41,44.63 R556.1 ; TP4.1 17.46,24.28 ; J14.1 16.7,26.98
  vias: v1(16.86,26.55) v1(16.85,25.91) v1(17.52,26.52) v1(17.49,25.9)
DIO0: length 7.2
  TOP w0.102: v1(7.12,34.04) 6.92,34.04 6.06,34.89 U1.49
  BOTTOM w0.102: v1(7.12,34.04) 7.12,34.16 TP49.1 8.89,34.85 10.1,36.06 10.1,36.7 SH40.1
DIO1: length 7
  TOP w0.102: v1(8.57,34.06) 8.09,33.58 7.02,33.58 6.56,34.04 6.56,34.05 6.34,34.27 6.33,34.27 6.21,34.39 U1.50
  BOTTOM w0.102: SH41.1 9.21,34.8 TP47.1 8.6,34.04 v1(8.57,34.06)
DIO4: length 9.4
  TOP w0.102: 5.49,32.89 5.94,32.89 v1(6.15,32.68)
  BOTTOM w0.102: v1(6.15,32.68) 5.61,33.22 5.61,34.19 5.97,34.55 6.76,34.55 7.94,35.73 8.54,35.73 9.51,36.7 TP43.1 9.53,36.82 10.27,37.56 10.27,37.89 SH46.1
DIO5/CLKOUT: length 2.9
  TOP w0.102: U1.54 5.83,32.39 6.18,32.04 6.18,31.97 v1(6.19,31.97)
  BOTTOM w0.102: v1(6.19,31.97) 6.22,32 TP42.1 7.39,32 7.64,32.26 SH45.1
EXTAL0: length 5.4
  TOP w0.076: U7.H8 13.1,17.46 13.17,17.39 13.96,17.39 14.09,17.26 14.09,16.29 14.16,16.22
  TOP w0.102: 14.16,16.22 14.19,16.2 15.43,16.2 X1.1 16.78,16.2 C23.2
EXTAL_32M: length 5.6
  TOP w0.102: U1.46 5.06,36.39 4.74,36.07 4.74,35.64 4.5,35.4 C21.1 3.86,35.03 2.1,35.03 1.28,35.85 Y1.1
JTAG_TCLK_K22F: length 13.1
  TOP w0.076: 9.63,13.63 9.85,13.85 9.85,14.07 9.99,14.21 10.13,14.21 10.13,14.22 10.2,14.22 10.34,14.36 10.34,14.43 10.35,14.43 10.35,14.57 10.49,14.71 10.84,14.71 U7.D3
  TOP w0.102: 9.63,13.63 8.76,12.76 8.4,12.76 7.67,13.49 7.01,13.49 v1(6.38,12.86)
  SIGNAL w0.102: J13.4 3.92,15.75 4.52,15.15 4.52,14.72 6.38,12.86 v1(6.38,12.86)
  BOTTOM w0.102: TP509.1 J13.4
JTAG_TDI_K22F: length 13.8
  TOP w0.076: U7.D4 10.95,15.46 10.7,15.72 9.99,15.72 9.84,15.86 9.84,16.07 9.7,16.22 9.42,16.22 8.86,16.78 8.57,16.78
  TOP w0.102: J13.8 3.3,13.27 4.54,13.27 4.76,13.48 4.76,16.56 4.97,16.78 8.57,16.78
  BOTTOM w0.102: TP511.1 J13.8
JTAG_TDO_K22F: length 22.1
  TOP w0.076: v1(11.39,17.93) 11.35,17.89 11.35,16.21 U7.E5
  SIGNAL w0.102: v1(11.39,17.93) 11.95,17.93 12.31,18.29 12.64,18.29 12.89,18.03 12.89,16.16 12.74,16.01 12.74,14.25 12.35,13.86 10.79,13.86 10.54,13.61 10.54,12.56 9.59,11.61 6.71,11.61 4.68,13.65 3.85,14.47 3.24,14.47 J13.6
  BOTTOM w0.102: TP510.1 J13.6
JTAG_TMS_K22F: length 13.1
  TOP w0.076: U7.D5 11,15.97 10.74,16.22 9.99,16.22 9.84,16.36 9.84,16.57 9.7,16.71 9.33,16.71 9.06,16.98 8.57,16.98
  TOP w0.102: R26.2 2.73,18.16 3.24,17.65 J13.2 3.27,16.98 8.57,16.98
  BOTTOM w0.102: TP508.1 J13.2
PTA0/SWD_CLK: length 2.6
  TOP w0.102: v1(10.4,30.04) 10.41,30.04 10.41,30.1 10.62,30.32 U1.10
  BOTTOM w0.102: 10.45,30.02 10.45,30.02 10.45,30.02 ; 10.45,30.02 10.48,30 10.48,29.72 SH47.2 ; 10.45,30.02 10.45,30.04 ; 10.45,30.04 10.45,30.72 TP36.1 ; 10.45,30.04 v1(10.4,30.04)
PTA1/UART0_RX: length 13.6
  TOP w0.102: v1(13.35,30.04) 13.34,30.04 12.83,30.04 12.62,30.25 U1.14 ; R89.2 13.84,20.67 v1(14.35,20.16)
  SIGNAL w0.102: v1(14.35,20.16) 14.35,20.43 14.34,20.44 14.34,21.01 14.92,21.6 14.92,23.72 13.52,25.12 13.52,29.87 v1(13.35,30.04)
  BOTTOM w0.102: TP113.1 v1(13.35,30.04)
PTA2/UART0_TX: length 13
  TOP w0.102: R88.1 12.74,19.66 11.73,20.67 v1(11.73,21.08) ; v1(12.14,30.08) 12.12,30.08 12.11,30.08 12.11,30.08 12.11,30.22 12.12,30.23 U1.13
  SIGNAL w0.102: v1(12.14,30.08) 12.12,30.08 12.11,30.08 12.11,29.43 12.61,28.92 12.61,28.43 11.95,27.76 11.95,21.99 11.72,21.77 11.72,21.09 v1(11.73,21.08)
  BOTTOM w0.102: TP114.1 11.75,30.44 12.11,30.08 12.12,30.08 v1(12.14,30.08)
PTA3/SWD_DIO: length 19.8
  TOP w0.102: v1(10.94,29.89) 10.94,30.18 11.12,30.36 U1.11 ; R25.1 16.45,26.67 J14.2 13.14,27.69 12.94,27.48 v1(12.33,27.48) ; R92.2 12.56,22 v1(12.1,21.54)
  SIGNAL w0.102: v1(12.33,27.48) 12.33,26.87 12.17,26.71 12.17,21.6 v1(12.1,21.54)
  BOTTOM w0.102: v1(12.33,27.48) 12.81,27.48 TP32.1 13.55,28.22 13.55,29.3 13.15,29.69 11.8,29.69 11.6,29.9 11.01,29.9 11.01,29.89 v1(10.94,29.89)
PTA12_K22F/LED: length 5.9
  TOP w0.102: R30.2 13.63,12.01 v1(13.45,12.19) ; U7.H6 v1(13.57,16.47)
  SIGNAL w0.102: v1(13.45,12.19) 13.67,12.41 13.67,13.79 13.21,14.25 13.21,15.75 13.57,16.1 v1(13.57,16.47)
PTA13_K22F/SW: length 25.5
  TOP w0.076: U7.G6 12.34,16.72 12.34,17.77 12.48,17.9 v1(12.48,17.91)
  TOP w0.102: SW2.1 1.41,22.48 v1(2.17,21.72)
  SIGNAL w0.102: v1(12.48,17.91) 12.48,17.9 12.48,14.34 12.2,14.07 10.71,14.07 10.34,13.7 10.34,12.78 10.05,12.49 7.29,12.49 4.9,14.88 4.9,17.04 3.71,18.23 3.71,18.23 3.64,18.3 3.64,20.24 v1(2.17,21.72)
  BOTTOM w0.102: TP30.1 2.04,21.84 v1(2.17,21.72)
PTA18: length 4.5
  TOP w0.102: v1(10.89,31.39) U1.15
  BOTTOM w0.102: v1(10.89,31.39) 10.89,31.39 10.09,31.39 9.23,32.26 SH45.2
PTA19: length 8.4
  TOP w0.102: v1(12.59,32.11) 12.59,32.11 12.81,31.89 U1.16
  BOTTOM w0.102: SH46.2 12.74,38.23 13.12,37.85 13.12,32.63 12.6,32.11 v1(12.59,32.11)
PTB0: length 13.6
  TOP w0.102: R31.2 14.82,24.77 v1(15.76,24.77) ; U1.17 13.61,32.39 13.96,32.74 13.96,32.94 14.64,33.63 v1(15.1,33.63)
  SIGNAL w0.102: v1(15.76,24.77) 15.58,24.94 15.58,24.94 14.14,26.39 14.14,33.05 14.71,33.63 v1(15.1,33.63)
PTB2: length 6
  TOP w0.102: R91.2 16.16,36.36 v1(15.76,36.36) 14.71,36.36 14.46,36.1 14.11,36.1 13.98,35.97 13.98,34.77 13.6,34.39 U1.21
  BOTTOM w0.102: TP117.1 15.91,35.81 15.76,35.97 v1(15.76,36.36)
PTB17: length 5.9
  TOP w0.102: R90.2 15.71,37.01 v1(15.65,37.07) 15.14,37.07 14.63,36.56 14.62,36.56 14.37,36.31 13.94,36.31 13.78,36.14 13.78,35.03 13.65,34.89 U1.22
  BOTTOM w0.102: TP116.1 15.65,36.8 v1(15.65,37.07)
PTC1: length 29.9
  TOP w0.076: 8.57,15.71 9.7,15.71 9.95,15.46 U7.B4
  TOP w0.102: U1.24 v1(12.6,35.89) ; v1(6.05,16.37) 7.47,16.37 8.13,15.71 8.57,15.71 8.57,15.71
  SIGNAL w0.102: v1(6.05,16.37) 6.03,16.4 6.03,16.79 4.25,18.57 4.25,22.22 v1(4.47,22.44) 5.58,23.55 5.58,24.54 7.52,26.49 8.57,26.49 9.23,27.15 9.23,29.13 8.78,29.58 8.78,32.23 12.45,35.89 v1(12.6,35.89)
PTC2: length 27.9
  TOP w0.076: 8.57,16.17 8.78,15.97 U7.A5
  TOP w0.102: v1(14.21,36.69) 13.77,36.69 13.48,36.39 U1.25 ; v1(8.54,16.21) 8.57,16.17
  SIGNAL w0.102: v1(14.21,36.69) 14.21,36.03 11.33,33.14 11.33,24.38 10.6,23.66 10.6,21.4 9.55,20.34 7.5,20.34 6.54,19.38 6.54,18.3 8.54,16.3 v1(8.54,16.21)
PTC3: length 1.8
  TOP w0.102: v1(12.56,36.88) 12.58,36.89 U1.26
  BOTTOM w0.102: v1(12.56,36.88) 12.23,37.21 SH40.2
PTC4: length 2.2
  TOP w0.102: U1.23 12.85,35.39 v1(12.59,35.13)
  BOTTOM w0.102: v1(12.59,35.13) 12.59,35.23 SH41.2
PTD4_SPI1_PCS0: length 33
  TOP w0.076: 8.57,15.22 10.34,15.22 10.6,14.96 U7.C3
  TOP w0.102: U1.27 12.89,37.39 12.61,37.67 v1(12.61,37.68) ; v1(6.03,15.09) 6.16,15.22 8.57,15.22
  SIGNAL w0.102: v1(12.61,37.68) 12.44,37.68 9.23,34.47 9.23,33.78 7.16,31.71 7.16,29.47 6.27,28.58 6.27,25.81 4,23.55 v1(3.72,23.55) 3.85,23.42 3.85,18.38 5.3,16.93 5.3,15.82 v1(6.03,15.09)
PTD5_SPI1_SCK: length 30.7
  TOP w0.102: v1(7.32,15.8) 7.66,15.46 U7.A4 ; U1.28 v1(13.25,38.77)
  SIGNAL w0.102: v1(13.25,38.77) 13.63,38.39 13.63,36.35 12.79,35.51 12.35,35.51 8.99,32.14 8.99,29.66 9.47,29.18 9.47,27.1 8.99,26.62 8.99,26.62 8.33,25.96 8.33,25.45 6.13,23.25 6.13,18.13 7.32,16.93 v1(7.32,15.8)
PTD6: length 13.6
  TOP w0.102: U1.29 12.62,38.74 13.93,40.06 16.04,40.06 16.14,40.16 16.14,40.18 16.14,42.47 16.75,43.08 SW1.1 16.22,45.69 v1(15.68,46.23)
  BOTTOM w0.102: TP23.1 v1(15.68,46.23) ; v1(15.68,46.23) 15.43,45.97 R556.2 ; v1(15.68,46.23) 15.43,46.48 C51.1
PTE0_SPI1_MISO: length 28.9
  TOP w0.076: 10.34,18.54 10.34,16.71 10.1,16.47 U7.B6
  TOP w0.102: U1.32 11.12,39.1 11.28,39.25 11.28,39.29 11.35,39.29 11.35,39.38 v1(11.34,39.38) ; 10.34,18.54 10.34,18.72 10.7,19.08 10.7,20.01 v1(10.37,20.34)
  SIGNAL w0.102: v1(11.34,39.38) 13.58,39.38 14.05,38.9 14.05,37.82 14.81,37.07 14.81,36.05 11.74,32.97 11.74,24.21 11.01,23.48 11.01,20.98 v1(10.37,20.34)
PTE1_SPI1_MOSI: length 32.9
  TOP w0.076: U7.A7 9.6,17 8.57,18.03
  TOP w0.102: 8.57,18.03 7.74,18.86 6.93,18.86 6.92,18.84 6.92,18.84 v1(6.92,18.84) ; U1.34 10.12,39.09 v1(10.29,39.26)
  SIGNAL w0.102: v1(6.92,18.84) 6.92,18.84 6.92,19.46 7.6,20.14 9.63,20.14 10.81,21.32 10.81,23.58 11.53,24.3 11.53,33.05 14.59,36.12 14.59,36.93 13.84,37.69 13.84,38.83 13.5,39.17 11.94,39.17 11.73,38.95 10.59,38.95 v1(10.29,39.26)
PTE18_I2C0_SDA: length 38.8
  TOP w0.076: 8.57,14.71 9.85,14.71 U7.B3
  TOP w0.102: v1(10.38,28.09) 10.71,28.09 R11.2 ; 8.57,14.71 8.31,14.45 v1(8.17,14.45) ; R53.2 15.56,38.12 16.06,38.62 16.06,38.61 v1(16.05,38.61)
  SIGNAL w0.102: v1(16.05,38.61) 16.14,38.51 16.14,34.98 15.59,34.42 14.98,34.42 14.64,34.42 13.53,33.31 13.53,30.86 12.97,30.3 12.97,29.88 12.97,29.88 12.97,29.87 13.31,29.52 13.32,29.52 13.32,26.64 v1(13.09,26.42) ; v1(8.17,14.45) 7.71,14.91 7.71,16.84 6.33,18.22 6.33,23.17 8.57,25.41 8.57,25.92 10.38,27.72 v1(10.38,28.09)
  BOTTOM w0.102: v1(13.09,26.42) 13.09,26.42 10.61,26.42 10.37,26.66 10.37,27.19 10.37,28.09 v1(10.38,28.09)
PTE19_I2C0_SCL: length 42.2
  TOP w0.076: 9.74,13.44 10.02,13.72 10.2,13.72 10.34,13.86 10.34,14.04 10.35,14.04 10.35,14.1 10.61,14.35 10.6,14.36 U7.C2
  TOP w0.102: v1(7.35,13.11) 7.9,12.56 8.86,12.56 9.74,13.44 ; v1(15.05,37.49) 14.67,37.49 14.54,37.62 R54.2 ; R15.1 9.69,26.42 v1(9.63,26.35) 9.27,26.35 9.16,26.47 6.65,26.47 v1(6.65,26.47)
  SIGNAL w0.102: v1(7.35,13.11) 6.49,13.97 6.49,15.19 5.59,16.09 5.59,16.93 4.05,18.48 4.05,23.04 4.33,23.32 4.33,23.59 6.65,25.91 v1(6.65,26.47) ; v1(12.89,25.83) 12.71,26.01 12.71,26.66 13.11,27.06 13.11,29.01 12.59,29.53 12.59,30.34 11.96,30.98 11.96,32.9 15.05,36 v1(15.05,37.49)
  BOTTOM w0.102: v1(9.63,26.35) 9.76,26.22 12.5,26.22 v1(12.89,25.83)
PTE30: length 3.4
  TOP w0.102: R85.1 8.83,30 8.75,30.08 8.75,30.08 v1(8.36,30.08) ; v1(9.84,30.02) 9.84,30.11 10.12,30.39 U1.9
  BOTTOM w0.102: v1(9.84,30.02) 9.78,30.08 v1(8.36,30.08)
R_SWD_DIO_TGTMCU: length 8.4
  TOP w0.102: R92.1 10.91,22.23 10.88,22.2 ; 10.88,22.2 10.88,21.51 10.73,21.36 8.67,21.36 8.67,21.36 8.6,21.44 8.6,22.05 U8.3 ; 10.88,22.2 10.88,22.56 10.71,22.73 10.05,22.73 9.93,22.85 9.93,23.84 10.08,23.99 U8.9 10.3,24.67 v1(10.64,24.32)
RESET_B_TGTMCU: length 13
  TOP w0.076: U7.A8 9.6,18.27 9.32,18.54
  TOP w0.102: 9.32,18.54 9.27,18.59 9.27,19.38 9.27,19.39 v1(9.27,19.38) ; v1(15.56,19.94) 16.12,19.94 R14.1 R17.2
  SIGNAL w0.102: v1(15.56,19.94) 15.2,19.58 15.2,18.77 14.87,18.44 13.48,18.44 12.76,19.15 12.36,19.15 11.61,18.4 9.53,18.4 9.27,18.66 v1(9.27,19.38)
RESET_B_XCVR: length 8.2
  TOP w0.102: U1.48 6.11,35.39 v1(6.18,35.32) ; v1(1.82,32.39) 1.88,32.45 R5.1
  SIGNAL w0.102: v1(6.18,35.32) 3.25,32.39 v1(1.82,32.39)
  BOTTOM w0.102: SH44.2 5.58,35.11 5.97,35.11 v1(6.18,35.32)
RESET_TGTMCU_B: length 39.4
  TOP w0.102: C60.1 R113.2 17.59,39.37 v1(16.7,40.26) 16.7,41.33 SW5.2 ; U1.33 10.62,38.96 10.86,39.19 10.86,39.58 v1(11.44,40.17) ; 16.19,20.7 15.56,20.7 v1(15.53,20.68) 15.99,20.68 R14.2
  SIGNAL w0.102: 17.91,33.5 18.15,33.73 18.15,38.81 v1(16.7,40.26) 16.45,40.26 11.54,40.26 v1(11.44,40.17) ; 17.91,33.5 16.16,33.5 J14.10 ; 17.91,33.5 18.05,33.37 18.05,23.93 17.82,23.7 15.76,23.7 15.53,23.47 15.53,21.34 v1(15.53,20.68)
  BOTTOM w0.102: TP35.1 15.99,33.32 J14.10
RFIO: length 1
  TOP w0.178: L9.1 7.62,39.53 U1.39
RFIO_EXT: length 2.7
  TOP w0.457: L2.2 8.51,44.85 C4.1 ; L2.2 C58.1 ; L2.2 C7.1
RST_K22F: length 45.8
  TOP w0.076: 12.33,18.54 12.1,18.31 U7.F8
  TOP w0.102: SW6.2 2.32,27.43 3.04,26.72 3.04,26.04 v1(3.04,26.04) 3.04,26.03 C62.1 ; 12.33,18.54 v1(12.48,18.69) ; R114.2 J13.10
  SIGNAL w0.102: v1(12.48,18.69) 12.56,18.69 13.12,18.14 13.12,16 12.97,15.85 12.97,14.21 13.42,13.75 13.42,12.82 13.2,12.6 11.7,12.6 10.51,11.41 6.5,11.41 5.97,11.94 J13.10 3.24,11.93 2.48,11.17 0.92,11.17 0.56,11.53 0.56,23.55 v1(3.04,26.04)
  BOTTOM w0.102: TP105.1 v1(3.04,26.04) ; TP512.1 J13.10
SDA_SPI0_SCK: length 21.2
  TOP w0.076: 9.9,12.95 9.9,13.15 10.6,13.85 U7.C1
  TOP w0.102: v1(7.87,25.69) 7.88,25.68 8.42,25.68 8.58,25.52 U8.12 ; 9.9,12.95 v1(9.9,12.87)
  SIGNAL w0.102: v1(7.87,25.69) 7.16,25.69 6.67,25.19 6.67,24.1 4.46,21.89 4.46,18.65 6.51,16.6 6.51,15.46 6.69,15.28 6.69,14.12 7.33,13.49 7.67,13.49 8.4,12.75 9.77,12.75 v1(9.9,12.87)
SDA_SPI0_SIN: length 18.8
  TOP w0.076: U7.A2 9.04,14.46 v1(8.88,14.3)
  TOP w0.102: U8.8 12.66,23.62 v1(12.66,23.62) ; v1(7.92,17.62) 7.19,17.62 7.04,17.78 R112.1
  SIGNAL w0.102: v1(12.66,23.62) 12.52,23.48 12.52,21.26 11.89,20.63 11.21,20.63 10.52,19.94 7.69,19.94 7.3,19.55 7.3,19 7.3,19 7.3,18.25 v1(7.92,17.62) 7.92,17.36 8.57,16.71 9.07,16.21 9.07,14.85 8.88,14.66 v1(8.88,14.3)
SDA_SPI0_SOUT: length 13.6
  TOP w0.076: U7.B2 9.95,14.46 9.7,14.22 9.44,14.22 8.93,13.7 8.57,13.7
  TOP w0.102: v1(5.65,21.32) 5.95,21.32 6.7,22.07 U8.2 ; 8.57,13.7 v1(8.23,13.7)
  SIGNAL w0.102: v1(8.23,13.7) 7.46,14.47 7.46,15.09 6.92,15.62 6.92,17.04 5.65,18.31 v1(5.65,19.25) v1(5.65,21.32)
SDA_SWD_EN: length 24.3
  TOP w0.076: 11.84,18.54 11.84,16.37 11.85,16.37 11.85,16.36 11.99,16.22 12.34,16.22 U7.G5
  TOP w0.102: 11.84,18.54 11.84,18.94 12,19.1 12,20.03 10.87,21.16 7.23,21.16 7.19,21.11 v1(6.8,20.72) 6.65,20.57 R106.2 ; U8.13 8.08,24.24 8.29,24.03 9.44,24.03 9.58,24.17 U8.10 9.58,25.2 9.58,25.2 v1(9.58,25.46)
  SIGNAL w0.102: v1(6.8,20.72) 6.98,20.55 9.44,20.55 10.38,21.49 10.38,23.67 9.58,24.47 v1(9.58,25.46)
SDA_SWD_OE_B: length 17.1
  TOP w0.076: 8.57,14.96 U7.A3
  TOP w0.102: v1(5.04,21.93) 6.15,21.93 6.4,22.19 6.4,22.75 6.77,23.12 ; 6.77,23.12 6.71,23.12 6.39,23.44 6.39,24.1 v1(6.09,24.41) 5.8,24.7 5.8,24.95 R105.1 ; 6.77,23.12 U8.1 ; 8.57,14.96 7.54,14.96 7.07,14.5 v1(7.07,14.48)
  SIGNAL w0.102: v1(7.07,14.48) 7.07,15.18 6.72,15.54 6.72,16.95 5.27,18.4 5.27,21.71 v1(5.04,21.93)
SWD_CLK_TGTMCU: length 5.7
  TOP w0.102: v1(12.23,28.6) 12.13,28.7 R93.2 13.05,29.21 13.3,28.96 J14.4
  BOTTOM w0.102: TP51.1 12.61,28.96 12.26,28.6 v1(12.23,28.6) 12,28.83 12,29.21
UART1_CTS_TGTMCU: length 28.9
  TOP w0.076: U7.C6 10.85,16.72 10.85,18.06 11.33,18.54
  TOP w0.102: 11.33,18.54 11.63,18.84 11.63,19.27 v1(11.62,19.28) ; R90.1 17.77,37.31 v1(17.77,37.48)
  SIGNAL w0.102: v1(17.77,37.48) 17.77,36.31 16.35,34.89 16.35,34.89 15.67,34.22 14.72,34.22 13.73,33.22 13.73,25.27 15.13,23.88 15.13,21.46 14.8,21.13 14.8,19.01 14.63,18.85 13.68,18.85 12.97,19.56 11.9,19.56 v1(11.62,19.28)
UART1_RTS_TGTMCU: length 29.6
  TOP w0.076: U7.B7 9.84,17.22 9.84,18.54
  TOP w0.102: v1(9.68,18.79) 9.84,18.63 9.84,18.54 ; v1(17.51,34.16) 17.51,34.17 17.93,34.59 17.93,35.6 R91.1
  SIGNAL w0.102: v1(9.68,18.79) 9.87,18.61 11.51,18.61 12.26,19.35 12.87,19.35 13.58,18.64 14.77,18.64 15,18.87 15,20.95 15.33,21.28 15.33,21.43 15.33,23.55 15.33,23.89 15.33,24.87 13.93,26.26 13.93,33.13 14.81,34.01 15.46,34.01 15.71,33.77 17.12,33.77 v1(17.51,34.16)
UART1_RX_TGTMCU: length 6.9
  TOP w0.076: U7.B8 10.1,18.54
  TOP w0.102: 10.1,18.54 10.1,19.09 v1(10.14,19.13) ; R89.1 13.84,19.65 v1(14.26,19.24)
  SIGNAL w0.102: v1(14.26,19.24) 13.59,19.24 13.07,19.76 10.77,19.76 v1(10.14,19.13)
UART1_TX_TGTMCU: length 5.3
  TOP w0.076: U7.C8 10.6,18.5 10.64,18.54
  TOP w0.102: R88.2 12.74,20.55 13.11,20.18 v1(13.24,20.18) ; 10.64,18.54 v1(11.08,18.99)
  BOTTOM w0.102: v1(11.08,18.99) 11.08,19.28 11.44,19.64 11.45,19.64 11.46,19.66 11.97,19.66 12.49,20.18 v1(13.24,20.18)
USBDM: length 8.3
  TOP w0.254: U7.D1 11.1,13.57 v1(10.96,13.44)
  TOP w0.292: R50.2 8.88,10.62 8.88,10.97 C38.1 9.21,11.89 v1(9.33,12.01)
  BOTTOM w0.292: v1(9.33,12.01) 8.91,11.59 8.91,11.09 9.06,10.94 10.26,10.94 11.11,11.79 11.11,13.32 10.98,13.46 10.93,13.46 10.95,13.44 11,13.44 11,13.44 v1(10.96,13.44)
USBDP: length 9.5
  TOP w0.254: U7.E1 11.6,13.59 v1(11.74,13.44)
  TOP w0.292: v1(8.06,12.01) 8.19,11.89 C37.1 8.45,11.05 8.45,10.54 R51.2
  BOTTOM w0.292: v1(8.06,12.01) 8.48,11.6 8.48,10.91 8.88,10.5 10.44,10.5 11.55,11.61 11.55,13.25 v1(11.74,13.44)
VR_ANA: length 4.3
  TOP w0.254: 4.13,38.74 4.36,38.51 4.36,38 4.96,37.39 U1.44 5.81,37.39 v1(6.19,37.77)
  BOTTOM w0.254: v1(6.19,37.77) 6.77,38.35 TP46.1
VR_DIG: length 3.6
  TOP w0.254: v1(6.1,36.89) U1.45 4.85,36.89 4.02,37.72 C28.1
  BOTTOM w0.102: v1(6.1,36.89) 6.1,36.89 TP48.1
VR_PA: length 4.1
  TOP w0.178: L11.1 5.69,41.45 C14.1 5.7,40.83 C16.1 5.68,39.92 5.68,39.2 5.46,38.99 v1(5.46,38.54) 6.1,38.54 U1.42
VUSB: length 10.1
  TOP w0.076: 10.84,13.84 10.59,13.59 10.59,13.29 10.87,13.01 11.08,13.01 11.35,13.27 11.35,14.21 U7.D2 10.84,14.21 10.84,13.84
  TOP w0.152: 11.02,12.74 11.03,12.74 11.03,13.01
  TOP w0.203: 11.02,13.01 11.03,13.01 ; 11.02,12.74 11.01,12.73
  TOP w0.254: D18.C 11.14,8.26 10.95,8.45 v1(10.95,9.13) 11.34,9.53 C49.1 11.34,9.88 11.01,10.21 11.01,12.73
  BOTTOM w0.254: v1(10.95,9.13) 11.39,9.13 TP104.1
XTAL0: length 5.1
  TOP w0.076: 13.68,18.54 12.6,17.47 U7.G8
  TOP w0.102: C24.2 17.06,18.6 X1.3 15.43,18.6 13.73,18.6 13.68,18.54
XTAL_32M: length 3.8
  TOP w0.102: U1.47 5.1,35.89 4.97,35.76 4.97,35.36 4.23,34.63 C22.1 3.34,34.38 Y1.3
N23869826: length 9.4
  TOP w0.102: 8.62,39.25 8.62,39.25 8.62,39.25 ; 8.62,39.25 v1(8.62,39.25) ; 8.62,39.25 U1.37
  BOTTOM w0.102: v1(8.62,39.25) 8.62,39.29 8.24,39.67 5.75,39.67 5.4,40.03 5.4,41.05 5.04,41.41 2.19,41.41 TP37.1
N23870337: length 2.9
  TOP w0.178: L11.2 7.27,41.19 7.48,41.19 C13.1 ; L9.2 C13.1 ; C13.1 7.68,41.12 C15.1
N23870339: length 2.6
  TOP w0.178: C46.1 8.45,41.93 7.75,41.93 C13.2 L5.1 C11.2
N23870349: length 3.3
  TOP w0.178: L5.2 8.51,43.33 C9.1 ; L5.2 L2.1 ; L5.2 C11.1 C7.2
N23913269: length 5.9
  TOP w0.102: v1(7.72,30.08) 7.8,30 7.8,29.47 R85.2
  BOTTOM w0.102: v1(7.72,30.08) 7.72,30.49 6.81,31.4 5.79,31.4 5.14,32.04 SH44.1
N23948926: length 2.9
  TOP w0.457: J49.1 4.19,45.72 C58.2
N23974000: length 3.3
  TOP w0.102: v1(14.26,25.32) 13.78,24.84 13.78,24.79 15,23.58 D12.C
  BOTTOM w0.102: TP21.1 14.8,24.79 v1(14.26,25.32)
N24026304: length 1.7
  TOP w0.457: C17.1 9.86,45.72 L3.1 C50.2
N24026588: length 3.7
  TOP w0.457: C20.1 L3.2 ANT1.2
N24037103: length 7.1
  TOP w0.102: v1(9.37,31.43) 9.36,31.43 9.12,31.19 U1.7 ; R11.1 10.9,26.88 v1(10.9,26.96)
  SIGNAL w0.102: v1(10.9,26.96) 10.9,26.97 11.06,27.13 11.06,28.83 10.25,29.64 9.68,29.64 9.37,29.96 v1(9.37,31.43)
N24037421: length 3.8
  TOP w0.102: R15.2 9.97,27.81 9.97,29.18 v1(9.92,29.22) 9.46,29.69 9.46,30.18 9.62,30.34 U1.8
N24069474: length 1.5
  TOP w0.102: v1(8.33,31.41) 8.62,31.12 U1.6
  BOTTOM w0.102: TP24.1 8.62,31.12 v1(8.33,31.41)
N24071066: length 1.7
  TOP w0.102: U1.51 6.18,33.89 v1(6.18,33.89)
  BOTTOM w0.102: TP44.1 6.92,33.3 6.33,33.89 v1(6.18,33.89)
N24071069: length 3.2
  TOP w0.102: U1.52 6.79,33.39 v1(7.5,32.68)
  BOTTOM w0.102: TP45.1 7.59,32.68 v1(7.5,32.68)
N24103085: length 6.5
  TOP w0.457: L6.1 14.24,7.52 v1(14.24,7.09) 14.21,7.09 14.16,7.14 13.14,7.14 12.83,6.83 J5.A1
  BOTTOM w0.457: TVS1.1 13.64,8.22 13.77,8.09 13.77,8.06 14.24,7.59 v1(14.24,7.09)
N24103119: length 13.6
  TOP w0.254: 14.13,2.6 J5.S2 15.03,0.82 ; 4.54,2.6 J5.S1 3.63,0.82 ; L7.1 2.49,9.5 ; L7.1 1.57,8.48 ; L7.1 3.42,8.48
  BOTTOM w0.254: 15.03,0.82 J5.S2 14.13,2.6 ; 3.63,0.82 J5.S1 4.54,2.6
N24103131: length 6.3
  TOP w0.292: 9.21,9.27 9.08,9.27 8.7,8.89 8.7,7.78 8.95,7.54 ; J5.A2 10.33,5.79 9.62,6.51 9.24,6.51 8.73,7.02 8.73,7.32 8.95,7.54 ; 8.95,7.54 v1(8.94,7.54)
  BOTTOM w0.203: TVS3.1 8.94,7.87 8.94,7.54 v1(8.94,7.54)
N24103151: length 5.6
  TOP w0.292: J5.A3 8.38,5.25 8.54,5.25 8.74,5.45 8.74,6.39 8.3,6.84 8.3,7.33 8.08,7.54 ; 8.08,7.54 8.27,7.72 8.27,9.2 8.19,9.27 ; 8.08,7.54 v1(8.03,7.54)
  BOTTOM w0.203: TVS2.1 8.03,7.87 v1(8.03,7.54)
N24103276: length 6.1
  TOP w0.457: L6.2 17.15,9.46 v1(16.83,9.78) 14.01,9.78 13.96,9.73 13.96,9.72 13.25,9.02 D18.A
N24103280: length 3
  TOP w0.254: v1(13.14,10.03) 13.63,10.52 R30.1 14.26,10.54 D8.C
  BOTTOM w0.254: v1(13.14,10.03) TP17.1
N24103316: length 2.7
  TOP w0.102: v1(14.54,22.35) 14.54,21.84 R10.1 15.67,21.72 D4.C
  BOTTOM w0.102: TP8.1 v1(14.54,22.35)
N24103468: length 2
  TOP w0.076: U7.A1 8.77,13.14 8.57,13.14
  TOP w0.102: 8.57,13.14 v1(8.55,13.14)
  BOTTOM w0.102: TP102.1 8.67,13.26 v1(8.55,13.14)
N24109842: length 7.5
  TOP w0.102: R93.1 11.11,28.42 11.87,27.66 11.87,26.16 11.58,25.86 10.92,25.86 v1(10.64,25.59) 10.37,25.86 9.36,25.86 9.08,25.58 U8.11

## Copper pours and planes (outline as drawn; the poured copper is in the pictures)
GND on TOP: 18.19,12.93 18.19,7.34 5.25,7.34 5.25,7.72 3.8,7.72 3.8,9.78 3.8,9.78 3.8,9.92 0.51,9.92 0.51,47.63 18.17,47.63 18.18,39.67 18.18,33.76 18.18,31.12 18.18,31.12 18.19,18.26 18.19,12.93 ; 4 cut-outs
GND on TOP: 6.61,47.63 6.61,46.54 1.46,46.54 1.46,43.18 0.52,43.18 0.52,47.63
GND on TOP: 11.96,46.68 11.96,47.65 11.99,47.63 17.31,47.63 17.31,46.68
GND on TOP: 0.62,44.65 5,44.65 5.02,44.63 5.02,43.52 4.68,43.18 1.38,43.18 0.62,43.93
GND on TOP: 6.56,37.66 6.54,37.68 6.54,38.04 10.67,38.04 10.67,36 12.22,36 12.22,31.76 7.91,31.76 7.91,31.41 6.56,31.41
GND on BOTTOM: 0.51,41.4 0.51,47.59 0.52,47.6 18.17,47.6 18.17,40.94 9.91,40.94 8.84,39.88 5.5,39.88 5.25,40.13 5.25,41 4.84,41.4
GND on GND: 0.51,3.7 0.51,47.62 18.16,47.62 18.16,3.51 16.17,1.52 16.06,1.52 15.05,0.51 3.7,0.51
GND on SIGNAL: 0.51,40.41 0.51,47.66 18.19,47.66 18.19,40.41
P3V3_K22F on BOTTOM: 0.51,7.34 0.51,21.72 0.52,21.72 0.52,29.72 4.51,29.72 7.66,26.57 12.56,26.57 15.12,24.01 16.23,24.01 16.42,23.82 16.42,23.03 16.84,22.61 18.11,22.61 18.17,22.54 18.17,7.34
P3V3_K22F on SIGNAL: 0.51,6.74 0.51,23.62 18.22,23.62 18.22,6.74
VCC on BOTTOM: 0.51,41.15 4.69,41.15 4.99,40.84 4.99,40.13 5.65,39.47 5.68,39.5 8.85,39.5 10.05,40.69 11.47,40.69 11.54,40.61 18.18,40.61 18.18,33.76 18.17,33.75 18.17,31.14 18.17,31.14 18.17,23.19 17.89,22.9 16.92,22.9 16.7,23.13 16.7,23.86 16.3,24.25 16.3,24.26 15.41,24.26 12.84,26.82 7.84,26.82 4.69,29.97 0.5,29.97 0.51,29.98
VCC on SIGNAL: 0.51,23.9 0.51,40.12 18.19,40.12 18.19,23.9
N24103119 on TOP: 3.68,0.51 0.64,3.56 0.64,9.36 0.63,9.64 0.66,9.66 3.59,9.66 3.59,7.6 3.8,7.4 4.9,7.4 5,7.3 5,3.33 13.64,3.33 13.64,6.55 18.03,6.55 18.03,3.55 14.99,0.51
N24103119 on BOTTOM: 3.68,0.51 0.64,3.56 0.64,6.55 5,6.55 13.64,6.55 18.03,6.55 18.03,3.49 15.05,0.51

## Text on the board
BOTTOM: 700-28746 | 07 OF 10 | BOTTOM LAYER
Ref Des/Assembly Bottom: 2 of 2 | ASSEMBLY BOTTOM
Board Geometry/Soldermask Bottom: 08 OF 10 | SOLDERMASK BOTTOM
Package Geometry/Pastemask Bottom: 09 OF 10 | PASTEMASK BOTTOM
Ref Des/Silkscreen Bottom: FCC ID XZZYYNNN | REV A | SCH-28746 | 700-28746 | S/N | 10 OF 10 | SILKSCREEN BOTTOM
TOP: 04 OF 10 | TOP LAYER
Ref Des/Assembly Top: 1 of 2 | ASSEMBLY TOP
Board Geometry/Soldermask Top: 03 OF 10 | SOLDERMASK TOP
Package Geometry/Pastemask Top: 02 OF 10 | PASTEMASK TOP
Ref Des/Silkscreen Top: K | RST | K22F | KW01 | USB-KW019032 | 01 OF 10 | SILKSCREEN TOP
GND: 05 OF 10 | INNER GROUND LAYER
SIGNAL: 06 OF 10 | INNER_LAYER_2
